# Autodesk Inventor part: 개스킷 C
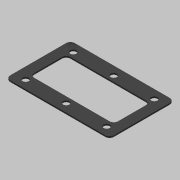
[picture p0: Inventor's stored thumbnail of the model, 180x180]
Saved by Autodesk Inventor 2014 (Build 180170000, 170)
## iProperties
Created: 2020-04
Part Number: 개스킷 C
Material: 고무
Document SubType Name: Modeling
Designer: mduedu
Density: 1 g/cm^3
Appearance: 고무 - 검은색 - 버전 1.1
Author: mduedu
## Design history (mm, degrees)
sketch "스케치1"
  geometry: L1 (37, 23)-(-37, 23); L2 (-37, 23)-(-37, -23); L3 (-37, -23)-(37, -23); L4 (37, -23)-(37, 23); L5 (37, 23)-(-37, -23); L6 (-37, 23)-(37, -23); L7 (30, 13)-(-30, 13); L8 (-30, 13)-(-30, -13); L9 (-30, -13)-(30, -13); L10 (30, -13)-(30, 13); L11 (30, 13)-(-30, -13); L12 (-30, 13)-(30, -13); 1 further point
  constraints: 24 end point, 4 midpoint, 4 parallel, 2 horizontal, 2 perpendicular
  dimensions: "d0" = 74 distance of L3.end L2.end; "d1" = 46 distance of L2.end L1.end; "d2" = 60 distance of L9.end L8.end; "d3" = 26 distance of L8.end L7.end
extrude "돌출1" new body sketch "스케치1" distance "d4" = 1; taper "d5" = 0 deg
fillet "모깎기1" dims "d6" = 3
fillet "모깎기2" dims "d7" = 3
sketch "스케치2"
  geometry: L1 (-29, -17)-(29, -17); L2 (29, -17)-(29, 17); L3 (29, 17)-(-29, 17); L4 (-29, 17)-(-29, -17); L5 (-29, -17)-(29, 17); L6 (29, -17)-(-29, 17); 7 further points
  constraints: 12 end point, 4 coincident, 4 midpoint, 2 parallel, 1 horizontal, 1 perpendicular
  dimensions: "d8" = 58 distance of L3.end L2.end; "d9" = 34 distance of L2.end L1.end
hole "구멍1" sketch "스케치2" at (-29, 17), (29, 17), (29, -17), (-29, -17), (0, 17), (0, -17) diameter "d10" = 4.5; stored, may be unused: countersink angle "d14" = 90 deg, drill point angle "d16" = 118 deg; dims "d11" = 6, "d12" = 4, "d13" = 2, "d15" = 8
node "솔리드1"
